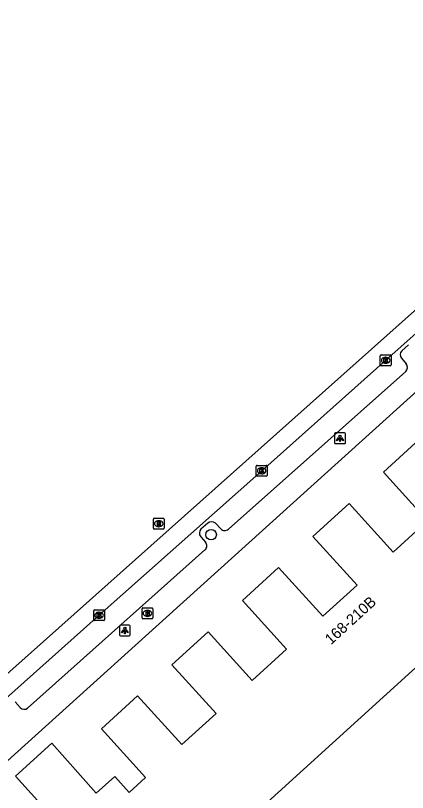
# Model space of a CAD drawing. Extents: x 162172 to 163187, y 382874 to 383684.
# Drawn here: x 162692.4 to 162728.8, y 383535.5 to 383607.5 of the extents above; entities that cross this region are included whole.
import ezdxf

# ---------------------------------------------------------------- set-up
doc = ezdxf.new("R2010")
doc.units = 0
for name, color, linetype in [('IMGEO_Boom', 7, 'Continuous'), ('IMGEO_Brandkraan', 7, 'Continuous'), ('IMGEO_Kolk', 7, 'Continuous'), ('IMGEO_Lichtpunt', 7, 'Continuous'), ('IMGEO_Pand', 7, 'Continuous'), ('IMGEO_Pand_nummerreeks', 7, 'Continuous'), ('IMGEO_Rijbaan_lokaal_gesloten', 7, 'Continuous'), ('IMGEO_Rioolput', 7, 'Continuous'), ('IMGEO_Voetpad_open', 7, 'Continuous')]:
    doc.layers.add(name, color=color, linetype=linetype)

msp = doc.modelspace()

# ---------------------------------------------------------------- linework, layer by layer
at = {"layer": 'IMGEO_Boom'}
msp.add_circle((162710.568, 383559.405), 0.489, dxfattribs=at)
at = {"layer": 'IMGEO_Brandkraan'}
for p, q in [((162704.163, 383551.686), (162704.163, 383552.538)), ((162704.238, 383552.612), (162705.09, 383552.612)), ((162705.164, 383552.538), (162705.164, 383551.686)), ((162704.674, 383551.832), (162704.649, 383551.832)), ((162704.651, 383552.392), (162704.676, 383552.392)), ((162705.09, 383551.612), (162704.238, 383551.612))]:
    msp.add_line(p, q, dxfattribs=at)
for points in [[(162704.163, 383551.686), (162704.163, 383552.538)], [(162704.238, 383552.612), (162705.09, 383552.612)], [(162705.164, 383552.538), (162705.164, 383551.686)], [(162704.511, 383552.312), (162704.511, 383551.912), (162704.724, 383551.912)], [(162704.742, 383552.312), (162704.511, 383552.312)], [(162704.69, 383552.231), (162704.636, 383552.231), (162704.636, 383552.155)], [(162704.636, 383552.155), (162704.689, 383552.155)], [(162704.698, 383552.079), (162704.636, 383552.079), (162704.636, 383551.998)], [(162704.636, 383551.998), (162704.698, 383551.998)], [(162705.09, 383551.612), (162704.238, 383551.612)]]:
    msp.add_lwpolyline(points, dxfattribs=at)
for centre, radius, start, end in [((162704.24, 383552.536), 0.0765, 91.55205, 178.44795), ((162704.24, 383552.536), 0.0765, 91.55205, 178.44795), ((162705.088, 383552.536), 0.0765, 1.55205, 88.44795), ((162705.088, 383552.536), 0.0765, 1.55205, 88.44795), ((162704.691, 383552.193), 0.0379, 267.82845, 90.93552), ((162704.699, 383552.038), 0.0404, 269.87594, 90.50774), ((162704.73, 383552.163), 0.251, 268.66757, 293.53466), ((162704.746, 383552.167), 0.145, 59.4692, 91.53667), ((162704.771, 383552.214), 0.0922, 285.51372, 58.15012), ((162704.776, 383552.022), 0.105, 301.31148, 78.98903), ((162704.24, 383551.688), 0.0765, 181.55205, 268.44795), ((162704.24, 383551.688), 0.0765, 181.55205, 268.44795), ((162705.088, 383551.688), 0.0765, 271.55205, 358.44795), ((162705.088, 383551.688), 0.0765, 271.55205, 358.44795)]:
    msp.add_arc(centre, radius, start, end, dxfattribs=at)
for centre, major_axis, ratio, start_param, end_param in [((162704.65, 383552.112), (-0.387, 0.002), 0.722429, 4.712389, 7.853982), ((162704.675, 383552.112), (-0.39, 0.002), 0.717154, 1.570796, 4.712389)]:
    msp.add_ellipse(centre, major_axis=major_axis, ratio=ratio, start_param=start_param, end_param=end_param, dxfattribs=at)
at = {"layer": 'IMGEO_Kolk'}
for p, q in [((162726.27, 383575.152), (162726.27, 383576.004)), ((162726.345, 383576.078), (162727.197, 383576.078)), ((162726.758, 383575.858), (162726.783, 383575.858)), ((162727.271, 383576.004), (162727.271, 383575.152)), ((162727.197, 383575.078), (162726.345, 383575.078)), ((162726.781, 383575.298), (162726.756, 383575.298)), ((162714.761, 383564.909), (162714.761, 383565.761)), ((162714.836, 383565.835), (162715.688, 383565.835)), ((162715.249, 383565.615), (162715.274, 383565.615)), ((162715.762, 383565.761), (162715.762, 383564.909)), ((162715.688, 383564.835), (162714.836, 383564.835)), ((162715.272, 383565.055), (162715.247, 383565.055)), ((162699.749, 383552.436), (162700.601, 383552.436)), ((162699.674, 383551.51), (162699.674, 383552.362)), ((162700.162, 383552.216), (162700.187, 383552.216)), ((162700.675, 383552.362), (162700.675, 383551.51)), ((162700.601, 383551.436), (162699.749, 383551.436)), ((162700.185, 383551.656), (162700.16, 383551.656))]:
    msp.add_line(p, q, dxfattribs=at)
for points in [[(162726.27, 383575.152), (162726.27, 383576.004)], [(162726.345, 383576.078), (162727.197, 383576.078)], [(162726.591, 383575.778), (162726.714, 383575.778), (162726.714, 383575.627), (162726.844, 383575.778), (162727.008, 383575.778), (162726.862, 383575.627), (162727.015, 383575.378), (162726.863, 383575.378), (162726.778, 383575.542), (162726.714, 383575.475), (162726.714, 383575.378), (162726.591, 383575.378), (162726.591, 383575.778)], [(162727.271, 383576.004), (162727.271, 383575.152)], [(162727.197, 383575.078), (162726.345, 383575.078)], [(162714.761, 383564.909), (162714.761, 383565.761)], [(162714.836, 383565.835), (162715.688, 383565.835)], [(162715.082, 383565.535), (162715.205, 383565.535), (162715.205, 383565.384), (162715.335, 383565.535), (162715.499, 383565.535), (162715.353, 383565.384), (162715.506, 383565.135), (162715.354, 383565.135), (162715.269, 383565.299), (162715.205, 383565.232), (162715.205, 383565.135), (162715.082, 383565.135), (162715.082, 383565.535)], [(162715.762, 383565.761), (162715.762, 383564.909)], [(162715.688, 383564.835), (162714.836, 383564.835)], [(162699.749, 383552.436), (162700.601, 383552.436)], [(162699.674, 383551.51), (162699.674, 383552.362)], [(162699.995, 383552.136), (162700.118, 383552.136), (162700.118, 383551.985), (162700.248, 383552.136), (162700.412, 383552.136), (162700.266, 383551.985), (162700.419, 383551.736), (162700.267, 383551.736), (162700.182, 383551.9), (162700.118, 383551.833), (162700.118, 383551.736), (162699.995, 383551.736), (162699.995, 383552.136)], [(162700.675, 383552.362), (162700.675, 383551.51)], [(162700.601, 383551.436), (162699.749, 383551.436)]]:
    msp.add_lwpolyline(points, dxfattribs=at)
for centre, start, end in [((162726.347, 383576.002), 91.55205, 178.44795), ((162726.347, 383576.002), 91.55205, 178.44795), ((162727.195, 383576.002), 1.55205, 88.44795), ((162727.195, 383576.002), 1.55205, 88.44795), ((162726.347, 383575.154), 181.55205, 268.44795), ((162726.347, 383575.154), 181.55205, 268.44795), ((162727.195, 383575.154), 271.55205, 358.44795), ((162727.195, 383575.154), 271.55205, 358.44795), ((162714.838, 383565.759), 91.55205, 178.44795), ((162714.838, 383565.759), 91.55205, 178.44795), ((162715.686, 383565.759), 1.55205, 88.44795), ((162715.686, 383565.759), 1.55205, 88.44795), ((162714.838, 383564.911), 181.55205, 268.44795), ((162714.838, 383564.911), 181.55205, 268.44795), ((162715.686, 383564.911), 271.55205, 358.44795), ((162715.686, 383564.911), 271.55205, 358.44795), ((162699.751, 383552.36), 91.55205, 178.44795), ((162699.751, 383552.36), 91.55205, 178.44795), ((162700.599, 383552.36), 1.55205, 88.44795), ((162700.599, 383552.36), 1.55205, 88.44795), ((162699.751, 383551.512), 181.55205, 268.44795), ((162699.751, 383551.512), 181.55205, 268.44795), ((162700.599, 383551.512), 271.55205, 358.44795), ((162700.599, 383551.512), 271.55205, 358.44795)]:
    msp.add_arc(centre, 0.0765, start, end, dxfattribs=at)
for centre, major_axis, ratio, start_param, end_param in [((162726.757, 383575.578), (-0.387, 0.002), 0.722429, 4.712389, 7.853982), ((162726.782, 383575.578), (-0.39, 0.002), 0.717154, 1.570796, 4.712389), ((162715.248, 383565.335), (-0.387, 0.002), 0.722429, 4.712389, 7.853982), ((162715.273, 383565.335), (-0.39, 0.002), 0.717154, 1.570796, 4.712389), ((162700.161, 383551.936), (-0.387, 0.002), 0.722429, 4.712389, 7.853982), ((162700.186, 383551.936), (-0.39, 0.002), 0.717154, 1.570796, 4.712389)]:
    msp.add_ellipse(centre, major_axis=major_axis, ratio=ratio, start_param=start_param, end_param=end_param, dxfattribs=at)
at = {"layer": 'IMGEO_Lichtpunt'}
for p, q in [((162722.032, 383568.749), (162722.032, 383567.942)), ((162722.032, 383568.749), (162722.032, 383567.942)), ((162722.934, 383568.844), (162722.126, 383568.844)), ((162722.934, 383568.844), (162722.126, 383568.844)), ((162723.028, 383567.942), (162723.028, 383568.749)), ((162723.028, 383567.942), (162723.028, 383568.749)), ((162722.126, 383567.848), (162722.934, 383567.848)), ((162722.126, 383567.848), (162722.934, 383567.848)), ((162702.973, 383551.029), (162702.165, 383551.029)), ((162702.973, 383551.029), (162702.165, 383551.029)), ((162702.071, 383550.934), (162702.071, 383550.127)), ((162702.071, 383550.934), (162702.071, 383550.127)), ((162703.067, 383550.127), (162703.067, 383550.934)), ((162703.067, 383550.127), (162703.067, 383550.934)), ((162702.165, 383550.033), (162702.973, 383550.033)), ((162702.165, 383550.033), (162702.973, 383550.033))]:
    msp.add_line(p, q, dxfattribs=at)
for points in [[(162722.406, 383568.413), (162722.445, 383568.385), (162722.257, 383568.123), (162722.219, 383568.15), (162722.406, 383568.413)], [(162722.508, 383568.365), (162722.555, 383568.365), (162722.555, 383568.043), (162722.508, 383568.043), (162722.508, 383568.365)], [(162722.618, 383568.385), (162722.656, 383568.412), (162722.843, 383568.15), (162722.804, 383568.122), (162722.618, 383568.385)], [(162702.445, 383550.598), (162702.484, 383550.57), (162702.296, 383550.308), (162702.258, 383550.335), (162702.445, 383550.598)], [(162702.547, 383550.55), (162702.594, 383550.55), (162702.594, 383550.228), (162702.547, 383550.228), (162702.547, 383550.55)], [(162702.657, 383550.57), (162702.695, 383550.597), (162702.882, 383550.335), (162702.843, 383550.307), (162702.657, 383550.57)]]:
    msp.add_lwpolyline(points, dxfattribs=at)
for centre in [(162722.531, 383568.547), (162702.57, 383550.732)]:
    msp.add_circle(centre, 0.0994, dxfattribs=at)
for centre, start, end in [((162722.126, 383568.749), 90, 180), ((162722.126, 383568.749), 90, 180), ((162722.934, 383568.749), 0, 90), ((162722.934, 383568.749), 0, 90), ((162722.126, 383567.942), 180, 270), ((162722.126, 383567.942), 180, 270), ((162722.934, 383567.942), 270, 0), ((162722.934, 383567.942), 270, 360), ((162702.165, 383550.934), 90, 180), ((162702.165, 383550.934), 90, 180), ((162702.973, 383550.934), 0, 90), ((162702.973, 383550.934), 0, 90), ((162702.165, 383550.127), 180, 270), ((162702.165, 383550.127), 180, 270), ((162702.973, 383550.127), 270, 0), ((162702.973, 383550.127), 270, 360)]:
    msp.add_arc(centre, 0.0946, start, end, dxfattribs=at)
at = {"layer": 'IMGEO_Pand'}
for points in [[(162668.172, 383494.324), (162674.468, 383500), (162707.707, 383529.967), (162709.05, 383528.485), (162742.01, 383558.381), (162740.673, 383559.855), (162769.856, 383586.324), (162773.559, 383589.683)], [(162729.91, 383568.257), (162726.552, 383565.202), (162730.657, 383560.69), (162727.471, 383557.792), (162723.366, 383562.304), (162720.008, 383559.248), (162724.113, 383554.736), (162720.933, 383551.842), (162716.828, 383556.354), (162713.47, 383553.299), (162717.575, 383548.787), (162714.394, 383545.893), (162710.289, 383550.405), (162706.924, 383547.343), (162711.029, 383542.831), (162707.856, 383539.944), (162703.751, 383544.456), (162700.393, 383541.4), (162704.494, 383536.897), (162702.971, 383535.511), (162701.626, 383536.991), (162699.91, 383535.431), (162695.797, 383540.079), (162692.423, 383537.028), (162696.515, 383532.504)]]:
    msp.add_lwpolyline(points, dxfattribs=at)
at = {"layer": 'IMGEO_Rijbaan_lokaal_gesloten'}
for points in [[(162575.926, 383440.306), (162578.565, 383444.116), (162582.633, 383450.258), (162596.824, 383462.654), (162637.568, 383498.615), (162689.014, 383544.186), (162734.284, 383584.449), (162759.283, 383606.749), (162778.679, 383623.816), (162796.954, 383640.261), (162813.125, 383654.021), (162813.712, 383654.475)], [(162656.498, 383513.075), (162662.451, 383518.384), (162669.665, 383524.825), (162683.894, 383537.45), (162700.174, 383551.938), (162715.261, 383565.336), (162726.771, 383575.578), (162743.824, 383590.746), (162757.962, 383603.266)]]:
    msp.add_lwpolyline(points, dxfattribs=at)
at = {"layer": 'IMGEO_Rioolput'}
for p, q in [((162705.213, 383560.001), (162705.213, 383560.853)), ((162705.288, 383560.927), (162706.14, 383560.927)), ((162705.701, 383560.707), (162705.726, 383560.707)), ((162706.214, 383560.853), (162706.214, 383560.001)), ((162706.14, 383559.927), (162705.288, 383559.927)), ((162705.724, 383560.147), (162705.699, 383560.147))]:
    msp.add_line(p, q, dxfattribs=at)
for points in [[(162705.213, 383560.001), (162705.213, 383560.853)], [(162705.288, 383560.927), (162706.14, 383560.927)], [(162705.802, 383560.625), (162705.55, 383560.627), (162705.55, 383560.227)], [(162705.55, 383560.227), (162705.674, 383560.227), (162705.674, 383560.389), (162705.685, 383560.389)], [(162705.728, 383560.546), (162705.674, 383560.546), (162705.674, 383560.465)], [(162705.674, 383560.465), (162705.726, 383560.465)], [(162705.732, 383560.36), (162705.803, 383560.227), (162705.943, 383560.227), (162705.878, 383560.353)], [(162706.214, 383560.853), (162706.214, 383560.001)], [(162706.14, 383559.927), (162705.288, 383559.927)]]:
    msp.add_lwpolyline(points, dxfattribs=at)
for centre, radius, start, end in [((162705.29, 383560.851), 0.0765, 91.55205, 178.44795), ((162705.29, 383560.851), 0.0765, 91.55205, 178.44795), ((162705.684, 383560.336), 0.0533, 26.02933, 88.69889), ((162705.71, 383560.654), 0.19, 274.7715, 282.96867), ((162705.734, 383560.45), 0.0964, 77.00612, 93.18647), ((162705.748, 383560.507), 0.0378, 276.66336, 79.67722), ((162705.801, 383560.515), 0.109, 350.36119, 89.41601), ((162705.799, 383560.515), 0.112, 277.58423, 350.98172), ((162705.783, 383560.3), 0.108, 29.51342, 73.79051), ((162706.138, 383560.851), 0.0765, 1.55205, 88.44795), ((162706.138, 383560.851), 0.0765, 1.55205, 88.44795), ((162705.29, 383560.003), 0.0765, 181.55205, 268.44795), ((162705.29, 383560.003), 0.0765, 181.55205, 268.44795), ((162706.138, 383560.003), 0.0765, 271.55205, 358.44795), ((162706.138, 383560.003), 0.0765, 271.55205, 358.44795)]:
    msp.add_arc(centre, radius, start, end, dxfattribs=at)
for centre, major_axis, ratio, start_param, end_param in [((162705.7, 383560.427), (-0.387, 0.002), 0.722429, 4.712389, 7.853982), ((162705.725, 383560.427), (-0.39, 0.002), 0.717154, 1.570796, 4.712389)]:
    msp.add_ellipse(centre, major_axis=major_axis, ratio=ratio, start_param=start_param, end_param=end_param, dxfattribs=at)
at = {"layer": 'IMGEO_Voetpad_open'}
for points in [[(162656.774, 383506.961), (162717.92, 383562.116), (162762.497, 383602.315), (162762.794, 383601.985), (162763.095, 383601.608)], [(162728.898, 383577.025), (162728.269, 383576.457)], [(162728.237, 383575.77), (162728.667, 383575.263)], [(162728.632, 383574.529), (162712.168, 383559.914)], [(162710.264, 383560.483), (162709.625, 383559.912)], [(162711.469, 383559.949), (162710.969, 383560.467)], [(162709.602, 383559.215), (162710.047, 383558.699)], [(162710.001, 383557.992), (162693.538, 383543.325)], [(162692.848, 383543.373), (162692.395, 383543.9)]]:
    msp.add_lwpolyline(points, dxfattribs=at)
for centre, radius, start, end in [((162728.597, 383576.097), 0.487, 132.41506, 222.2512), ((162728.244, 383574.915), 0.547, 315.09755, 39.44241), ((162710.607, 383560.066), 0.54, 47.92963, 129.47016), ((162709.998, 383559.551), 0.519, 135.90226, 220.31776), ((162711.836, 383560.272), 0.488, 221.36936, 312.89765), ((162709.682, 383558.368), 0.493, 310.29622, 42.25853), ((162693.219, 383543.726), 0.512, 223.5741, 308.46714)]:
    msp.add_arc(centre, radius, start, end, dxfattribs=at)

# ---------------------------------------------------------------- texts
at = {"layer": 'IMGEO_Pand_nummerreeks'}
msp.add_text('168-210B', height=1, rotation=42.30417, dxfattribs=at).set_placement((162721.685, 383549.146))

doc.saveas('drawing.dxf')
